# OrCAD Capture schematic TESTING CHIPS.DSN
size A; title: Battery Adapter; rev: 1; company: Vuong D. Tran
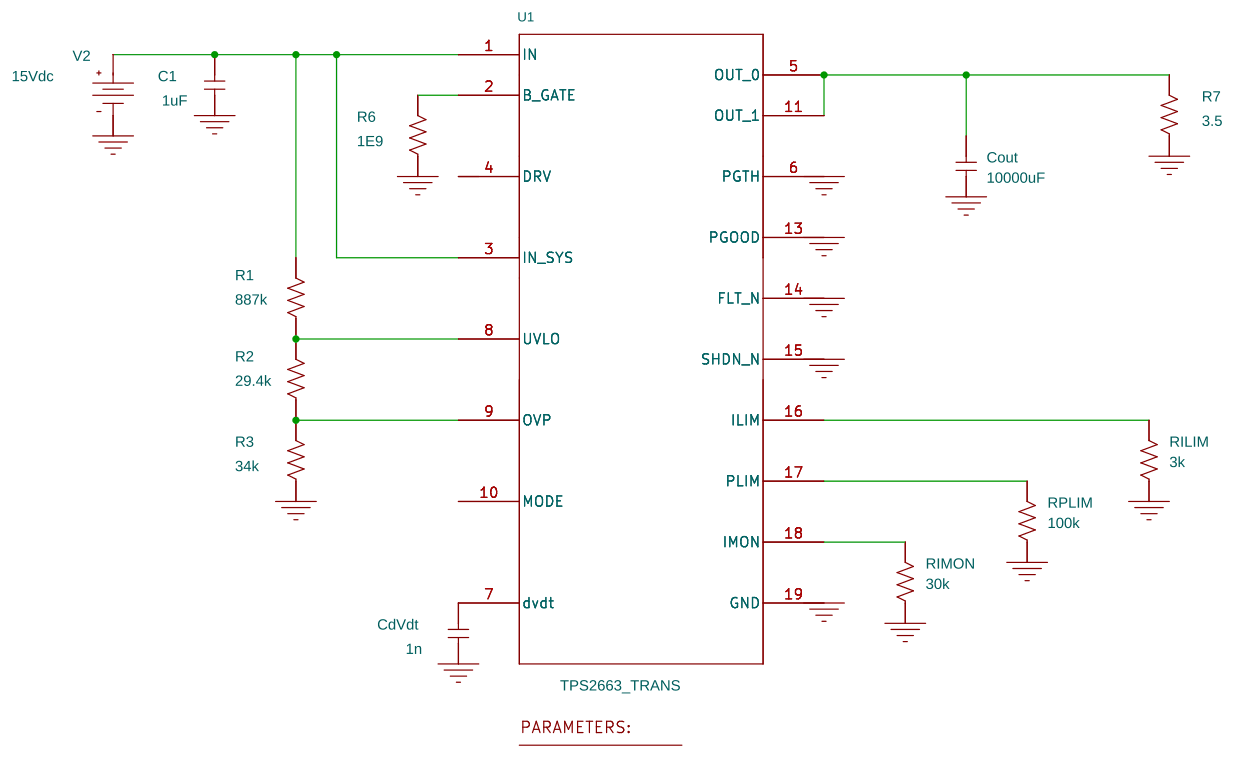
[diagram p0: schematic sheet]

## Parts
1  PARAM
C1  1uF  [cap196]
CdVdt  1n  [cap196]
Cout  10000uF  [cap196]
R1  887k  [AXRC05]
R2  29.4k  [AXRC05]
R3  34k  [AXRC05]
R6  1E9  [AXRC05]
R7  3.5  [AXRC05]
RILIM  3k  [AXRC05]
RIMON  30k  [AXRC05]
RPLIM  100k  [AXRC05]
U1  TPS2663_TRANS  [DRC0010J]
V2  VDC

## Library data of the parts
1 = PARAM: Adjustable_Output_Power_Limit: 0; Overload_Respond: 0; Overvoltage_Protection: 0
C1 CdVdt Cout = C
R1-R3 R6 R7 RILIM RIMON RPLIM = R
U1 = TPS2663_TRANS_2: PSpiceTemplate: X^@REFDES  %B_GATE %DRV %dvdt %FLT_N %GND %ILIM %IMON %IN %IN_SYS %MODE %OUT_0 %OUT_1 %OVP %PGOOD %PGTH %PLIM %SHDN_N %UVLO @MODEL
V2 = VDC: DC: 15Vdc

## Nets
0: C1.1 CdVdt.1 Cout.1 R3.1 R6.1 R7.1 RILIM.1 RIMON.1 RPLIM.1 U1.6(PGTH) U1.13(PGOOD) U1.14(FLT_N) U1.15(SHDN_N) U1.19(GND) V2.1(-)
MODE: U1.10(MODE)
N26823: C1.2 R1.2 U1.1(IN) U1.3(IN_SYS) V2.0(+)
N26857: Cout.2 R7.2 U1.5(OUT_0) U1.11(OUT_1)
N26875: R6.2 U1.2(B_GATE)
N27021: R1.1 R2.2 U1.8(UVLO)
N27055: R2.1 R3.2 U1.9(OVP)
N27061: RILIM.2 U1.16(ILIM)
N27107: RPLIM.2 U1.17(PLIM)
N27149: RIMON.2 U1.18(IMON)
N27259: CdVdt.2 U1.7(dvdt)

Not connected (* = marked no-connect by the designer): U1 4(DRV)
